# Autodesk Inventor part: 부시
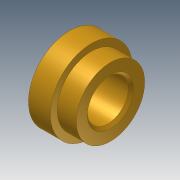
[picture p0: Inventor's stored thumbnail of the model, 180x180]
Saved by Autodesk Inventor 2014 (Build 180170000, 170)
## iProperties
Created: 2011-04
Part Number: 부시
Document SubType Name: Modeling
Designer: 한국산업디자인학원 [http://gmhk.co.kr]
Density: 1 g/cm^3
Material: 일반
Appearance: 황동 - 새틴
Author: pww
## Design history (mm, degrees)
sketch "스케치1"
  geometry: L1 (0, 0)-(15, 0); L2 (0, 7.5)-(15, 7.5); L3 (15, 7.5)-(15, 12.5); L4 (15, 12.5)-(8, 12.5); L5 (8, 12.5)-(8, 15); L6 (8, 15)-(0, 15); L7 (0, 15)-(0, 7.5)
  constraints: 14 end point, 4 parallel, 2 vertical alignment, 1 horizontal, 1 perpendicular, 1 vertical
  dimensions: "d0" = 15 distance of L1.start L1.end; "d1" = 15 diameter of L2 L1; "d2" = 25 diameter of L4 L1; "d3" = 8 distance of L5.end L6.end; "d4" = 30 diameter of L6 L1
revolve "회전1" sketch "스케치1" stored, may be unused: angle "d5" = 90 deg
chamfer "모따기1" distance "d6" = 1; stored, may be unused: second distance "d7" = 2, angle "d8" = 45 deg
node "솔리드1"
